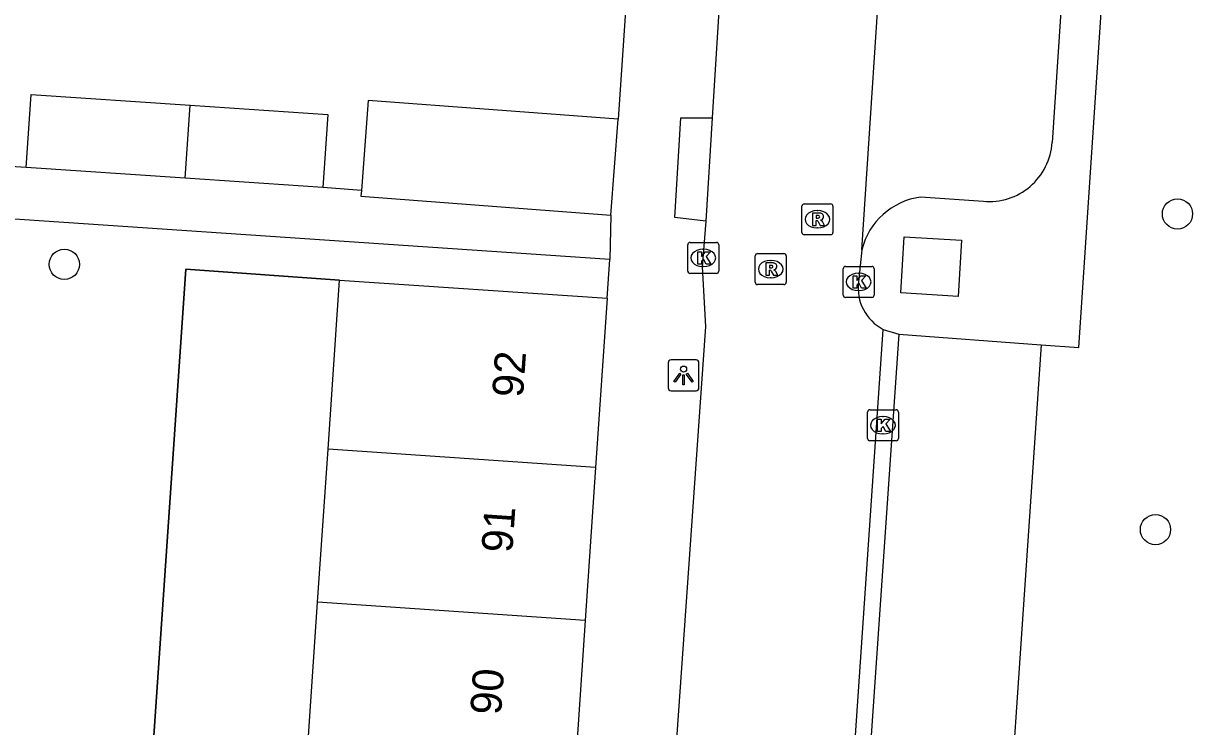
# Model space of a CAD drawing. Extents: x 161848 to 162726, y 385382 to 386521.
# Drawn here: x 162098.13 to 162135.92, y 385694.21 to 385716.95 of the extents above; entities that cross this region are included whole.
import ezdxf

# ---------------------------------------------------------------- set-up
doc = ezdxf.new("R2010")
doc.units = 0
for name, color, linetype in [('IMGEO_Boom', 7, 'Continuous'), ('IMGEO_Erf', 7, 'Continuous'), ('IMGEO_Kolk', 7, 'Continuous'), ('IMGEO_Lichtpunt', 7, 'Continuous'), ('IMGEO_Muur', 7, 'Continuous'), ('IMGEO_Pand', 7, 'Continuous'), ('IMGEO_Pand_nummerreeks', 7, 'Continuous'), ('IMGEO_Parkeervlak_open', 7, 'Continuous'), ('IMGEO_Rijbaan_lokaal_open', 7, 'Continuous'), ('IMGEO_Rioolput', 7, 'Continuous'), ('IMGEO_Voetpad_open', 7, 'Continuous')]:
    doc.layers.add(name, color=color, linetype=linetype)

msp = doc.modelspace()

# ---------------------------------------------------------------- linework, layer by layer
at = {"layer": 'IMGEO_Boom'}
for centre in [(162135.433, 385710.785), (162099.455, 385709.155), (162134.722, 385700.577)]:
    msp.add_circle(centre, 0.489, dxfattribs=at)
at = {"layer": 'IMGEO_Erf'}
msp.add_lwpolyline([(162108.35, 385708.642), (162103.379, 385708.994), (162101.257, 385678.025), (162106.241, 385677.689)], dxfattribs=at)
at = {"layer": 'IMGEO_Kolk'}
for p, q in [((162119.605, 385708.937), (162119.605, 385709.789)), ((162119.68, 385709.863), (162120.532, 385709.863)), ((162120.093, 385709.643), (162120.118, 385709.643)), ((162120.606, 385709.789), (162120.606, 385708.937)), ((162120.532, 385708.863), (162119.68, 385708.863)), ((162120.116, 385709.083), (162120.091, 385709.083)), ((162124.627, 385708.162), (162124.627, 385709.014)), ((162124.702, 385709.088), (162125.554, 385709.088)), ((162125.115, 385708.868), (162125.14, 385708.868)), ((162125.628, 385709.014), (162125.628, 385708.162)), ((162125.554, 385708.088), (162124.702, 385708.088)), ((162125.138, 385708.308), (162125.113, 385708.308)), ((162125.414, 385703.525), (162125.414, 385704.377)), ((162125.489, 385704.451), (162126.341, 385704.451)), ((162126.415, 385704.377), (162126.415, 385703.525)), ((162125.902, 385704.231), (162125.927, 385704.231)), ((162125.925, 385703.671), (162125.9, 385703.671)), ((162126.341, 385703.451), (162125.489, 385703.451))]:
    msp.add_line(p, q, dxfattribs=at)
for points in [[(162119.605, 385708.937), (162119.605, 385709.789)], [(162119.68, 385709.863), (162120.532, 385709.863)], [(162119.926, 385709.563), (162120.049, 385709.563), (162120.049, 385709.412), (162120.179, 385709.563), (162120.343, 385709.563), (162120.197, 385709.412), (162120.35, 385709.163), (162120.198, 385709.163), (162120.113, 385709.327), (162120.049, 385709.26), (162120.049, 385709.163), (162119.926, 385709.163), (162119.926, 385709.563)], [(162120.606, 385709.789), (162120.606, 385708.937)], [(162120.532, 385708.863), (162119.68, 385708.863)], [(162124.627, 385708.162), (162124.627, 385709.014)], [(162124.702, 385709.088), (162125.554, 385709.088)], [(162124.948, 385708.788), (162125.071, 385708.788), (162125.071, 385708.637), (162125.201, 385708.788), (162125.365, 385708.788), (162125.219, 385708.637), (162125.372, 385708.388), (162125.22, 385708.388), (162125.135, 385708.552), (162125.071, 385708.485), (162125.071, 385708.388), (162124.948, 385708.388), (162124.948, 385708.788)], [(162125.628, 385709.014), (162125.628, 385708.162)], [(162125.554, 385708.088), (162124.702, 385708.088)], [(162125.414, 385703.525), (162125.414, 385704.377)], [(162125.489, 385704.451), (162126.341, 385704.451)], [(162126.415, 385704.377), (162126.415, 385703.525)], [(162125.735, 385704.151), (162125.858, 385704.151), (162125.858, 385704), (162125.988, 385704.151), (162126.152, 385704.151), (162126.006, 385704), (162126.159, 385703.751), (162126.007, 385703.751), (162125.922, 385703.915), (162125.858, 385703.848), (162125.858, 385703.751), (162125.735, 385703.751), (162125.735, 385704.151)], [(162126.341, 385703.451), (162125.489, 385703.451)]]:
    msp.add_lwpolyline(points, dxfattribs=at)
for centre, start, end in [((162119.682, 385709.787), 91.552, 178.448), ((162119.682, 385709.787), 91.552, 178.448), ((162120.53, 385709.787), 1.552, 88.448), ((162120.53, 385709.787), 1.552, 88.448), ((162119.682, 385708.939), 181.552, 268.448), ((162119.682, 385708.939), 181.552, 268.448), ((162120.53, 385708.939), 271.552, 358.448), ((162120.53, 385708.939), 271.552, 358.448), ((162124.704, 385709.012), 91.552, 178.448), ((162124.704, 385709.012), 91.552, 178.448), ((162125.552, 385709.012), 1.552, 88.448), ((162125.552, 385709.012), 1.552, 88.448), ((162124.704, 385708.164), 181.552, 268.448), ((162124.704, 385708.164), 181.552, 268.448), ((162125.552, 385708.164), 271.552, 358.448), ((162125.552, 385708.164), 271.552, 358.448), ((162125.491, 385704.375), 91.552, 178.448), ((162125.491, 385704.375), 91.552, 178.448), ((162126.339, 385704.375), 1.552, 88.448), ((162126.339, 385704.375), 1.552, 88.448), ((162125.491, 385703.527), 181.552, 268.448), ((162125.491, 385703.527), 181.552, 268.448), ((162126.339, 385703.527), 271.552, 358.448), ((162126.339, 385703.527), 271.552, 358.448)]:
    msp.add_arc(centre, 0.0765, start, end, dxfattribs=at)
for centre, major_axis, ratio, start_param, end_param in [((162120.092, 385709.363), (-0.387, 0.002), 0.722429, 4.712389, 7.853982), ((162120.117, 385709.363), (-0.39, 0.002), 0.717154, 1.570796, 4.712389), ((162125.114, 385708.588), (-0.387, 0.002), 0.722429, 4.712389, 7.853982), ((162125.139, 385708.588), (-0.39, 0.002), 0.717154, 1.570796, 4.712389), ((162125.901, 385703.951), (-0.387, 0.002), 0.722429, 4.712389, 7.853982), ((162125.926, 385703.951), (-0.39, 0.002), 0.717154, 1.570796, 4.712389)]:
    msp.add_ellipse(centre, major_axis=major_axis, ratio=ratio, start_param=start_param, end_param=end_param, dxfattribs=at)
at = {"layer": 'IMGEO_Lichtpunt'}
for p, q in [((162118.971, 385705.969), (162118.971, 385705.162)), ((162118.971, 385705.969), (162118.971, 385705.162)), ((162119.873, 385706.064), (162119.065, 385706.064)), ((162119.873, 385706.064), (162119.065, 385706.064)), ((162119.967, 385705.162), (162119.967, 385705.969)), ((162119.967, 385705.162), (162119.967, 385705.969)), ((162119.065, 385705.068), (162119.873, 385705.068)), ((162119.065, 385705.068), (162119.873, 385705.068))]:
    msp.add_line(p, q, dxfattribs=at)
for points in [[(162119.345, 385705.633), (162119.384, 385705.605), (162119.196, 385705.343), (162119.158, 385705.37), (162119.345, 385705.633)], [(162119.447, 385705.585), (162119.494, 385705.585), (162119.494, 385705.263), (162119.447, 385705.263), (162119.447, 385705.585)], [(162119.557, 385705.605), (162119.595, 385705.632), (162119.782, 385705.37), (162119.743, 385705.342), (162119.557, 385705.605)]]:
    msp.add_lwpolyline(points, dxfattribs=at)
msp.add_circle((162119.47, 385705.767), 0.0994, dxfattribs=at)
for centre, start, end in [((162119.065, 385705.969), 90, 180), ((162119.065, 385705.969), 90, 180), ((162119.873, 385705.969), 0, 90), ((162119.873, 385705.969), 0, 90), ((162119.065, 385705.162), 180, 270), ((162119.065, 385705.162), 180, 270), ((162119.873, 385705.162), 270, 0), ((162119.873, 385705.162), 270, 360)]:
    msp.add_arc(centre, 0.0946, start, end, dxfattribs=at)
at = {"layer": 'IMGEO_Muur'}
msp.add_lwpolyline([(162106.241, 385677.689), (162101.257, 385678.025), (162103.379, 385708.994), (162108.35, 385708.642)], dxfattribs=at)
at = {"layer": 'IMGEO_Pand'}
for points in [[(162098.226, 385712.287), (162098.387, 385714.653), (162103.522, 385714.305)], [(162117.352, 385713.847), (162109.275, 385714.458), (162109.055, 385711.543)], [(162103.365, 385711.939), (162103.522, 385714.305)], [(162103.522, 385714.305), (162107.971, 385714.003), (162107.81, 385711.637)], [(162117.118, 385710.751), (162117.352, 385713.847)], [(162103.365, 385711.939), (162098.226, 385712.287)], [(162107.81, 385711.637), (162103.365, 385711.939)], [(162109.055, 385711.543), (162109.041, 385711.363), (162117.118, 385710.751)], [(162128.448, 385709.937), (162128.341, 385708.12), (162126.487, 385708.23), (162126.595, 385710.046), (162128.448, 385709.937)], [(162107.978, 385703.173), (162108.35, 385708.642)], [(162108.35, 385708.642), (162117.001, 385708.064)], [(162117.001, 385708.064), (162116.627, 385702.583)], [(162107.641, 385698.23), (162107.978, 385703.173)], [(162116.627, 385702.583), (162107.978, 385703.173)], [(162116.627, 385702.583), (162116.29, 385697.64)], [(162107.291, 385693.104), (162107.641, 385698.23)], [(162116.29, 385697.64), (162107.641, 385698.23)], [(162116.29, 385697.64), (162115.94, 385692.515)]]:
    msp.add_lwpolyline(points, dxfattribs=at)
at = {"layer": 'IMGEO_Parkeervlak_open'}
msp.add_lwpolyline([(162131.03, 385706.552), (162129.353, 385681.999)], dxfattribs=at)
at = {"layer": 'IMGEO_Rijbaan_lokaal_open'}
for points in [[(162120.507, 385734.873), (162121.694, 385734.795), (162120.393, 385713.89)], [(162125.234, 385709.628), (162126.713, 385732.225)], [(162120.393, 385713.89), (162120.186, 385710.552)], [(162120.186, 385710.552), (162120.068, 385709.079), (162120.176, 385707.147), (162118.427, 385682.147)], [(162125.234, 385709.628), (162125.128, 385708.588)], [(162124.197, 385681.746), (162125.923, 385707.05)], [(162126.424, 385706.892), (162124.693, 385681.723)], [(162125.923, 385707.05), (162126.424, 385706.892)]]:
    msp.add_lwpolyline(points, dxfattribs=at)
msp.add_arc((162126.618, 385708.384), 1.504, 172.187, 242.4823, dxfattribs=at)
at = {"layer": 'IMGEO_Rioolput'}
for p, q in [((162123.371, 385711.112), (162124.223, 385711.112)), ((162123.296, 385710.186), (162123.296, 385711.038)), ((162123.784, 385710.892), (162123.809, 385710.892)), ((162124.297, 385711.038), (162124.297, 385710.186)), ((162123.807, 385710.332), (162123.782, 385710.332)), ((162124.223, 385710.112), (162123.371, 385710.112)), ((162121.786, 385708.575), (162121.786, 385709.427)), ((162121.861, 385709.501), (162122.713, 385709.501)), ((162122.274, 385709.281), (162122.299, 385709.281)), ((162122.787, 385709.427), (162122.787, 385708.575)), ((162122.713, 385708.501), (162121.861, 385708.501)), ((162122.297, 385708.721), (162122.272, 385708.721))]:
    msp.add_line(p, q, dxfattribs=at)
for points in [[(162123.371, 385711.112), (162124.223, 385711.112)], [(162123.296, 385710.186), (162123.296, 385711.038)], [(162123.885, 385710.81), (162123.633, 385710.812), (162123.633, 385710.412)], [(162123.811, 385710.731), (162123.757, 385710.731), (162123.757, 385710.65)], [(162124.297, 385711.038), (162124.297, 385710.186)], [(162123.633, 385710.412), (162123.757, 385710.412), (162123.757, 385710.574), (162123.768, 385710.574)], [(162123.757, 385710.65), (162123.809, 385710.65)], [(162123.815, 385710.545), (162123.886, 385710.412), (162124.026, 385710.412), (162123.961, 385710.538)], [(162124.223, 385710.112), (162123.371, 385710.112)], [(162121.786, 385708.575), (162121.786, 385709.427)], [(162121.861, 385709.501), (162122.713, 385709.501)], [(162122.375, 385709.199), (162122.123, 385709.201), (162122.123, 385708.801)], [(162122.787, 385709.427), (162122.787, 385708.575)], [(162122.123, 385708.801), (162122.247, 385708.801), (162122.247, 385708.963), (162122.258, 385708.963)], [(162122.301, 385709.12), (162122.247, 385709.12), (162122.247, 385709.039)], [(162122.247, 385709.039), (162122.299, 385709.039)], [(162122.305, 385708.934), (162122.376, 385708.801), (162122.516, 385708.801), (162122.451, 385708.927)], [(162122.713, 385708.501), (162121.861, 385708.501)]]:
    msp.add_lwpolyline(points, dxfattribs=at)
for centre, radius, start, end in [((162123.373, 385711.036), 0.0765, 91.552, 178.448), ((162123.373, 385711.036), 0.0765, 91.552, 178.448), ((162124.221, 385711.036), 0.0765, 1.552, 88.448), ((162124.221, 385711.036), 0.0765, 1.552, 88.448), ((162123.817, 385710.635), 0.0964, 77.0061, 93.1865), ((162123.831, 385710.692), 0.0378, 276.6634, 79.6772), ((162123.884, 385710.7), 0.109, 350.3612, 89.416), ((162123.882, 385710.7), 0.112, 277.5842, 350.9817), ((162123.767, 385710.521), 0.0533, 26.0293, 88.6989), ((162123.793, 385710.839), 0.19, 274.7715, 282.9687), ((162123.866, 385710.485), 0.108, 29.5134, 73.7905), ((162123.373, 385710.188), 0.0765, 181.552, 268.448), ((162123.373, 385710.188), 0.0765, 181.552, 268.448), ((162124.221, 385710.188), 0.0765, 271.552, 358.448), ((162124.221, 385710.188), 0.0765, 271.552, 358.448), ((162121.863, 385709.425), 0.0765, 91.552, 178.448), ((162121.863, 385709.425), 0.0765, 91.552, 178.448), ((162122.374, 385709.089), 0.109, 350.3612, 89.416), ((162122.711, 385709.425), 0.0765, 1.552, 88.448), ((162122.711, 385709.425), 0.0765, 1.552, 88.448), ((162122.257, 385708.91), 0.0533, 26.0293, 88.6989), ((162122.283, 385709.228), 0.19, 274.7715, 282.9687), ((162122.307, 385709.024), 0.0964, 77.0061, 93.1865), ((162122.321, 385709.081), 0.0378, 276.6634, 79.6772), ((162122.372, 385709.089), 0.112, 277.5842, 350.9817), ((162122.356, 385708.874), 0.108, 29.5134, 73.7905), ((162121.863, 385708.577), 0.0765, 181.552, 268.448), ((162121.863, 385708.577), 0.0765, 181.552, 268.448), ((162122.711, 385708.577), 0.0765, 271.552, 358.448), ((162122.711, 385708.577), 0.0765, 271.552, 358.448)]:
    msp.add_arc(centre, radius, start, end, dxfattribs=at)
for centre, major_axis, ratio, start_param, end_param in [((162123.783, 385710.612), (-0.387, 0.002), 0.722429, 4.712389, 7.853982), ((162123.808, 385710.612), (-0.39, 0.002), 0.717154, 1.570796, 4.712389), ((162122.273, 385709.001), (-0.387, 0.002), 0.722429, 4.712389, 7.853982), ((162122.298, 385709.001), (-0.39, 0.002), 0.717154, 1.570796, 4.712389)]:
    msp.add_ellipse(centre, major_axis=major_axis, ratio=ratio, start_param=start_param, end_param=end_param, dxfattribs=at)
at = {"layer": 'IMGEO_Voetpad_open'}
for points in [[(162118.638, 385732.761), (162118.056, 385724.2), (162117.352, 385713.847)], [(162131.03, 385706.552), (162132.244, 385706.463), (162133.941, 385731.866)], [(162132.371, 385728.103), (162131.381, 385713.099)], [(162120.186, 385710.552), (162119.185, 385710.667), (162119.376, 385713.898), (162120.393, 385713.89)], [(162117.085, 385709.313), (162057.615, 385713.34)], [(162098.226, 385712.287), (162095.838, 385712.439)], [(162109.055, 385711.543), (162107.81, 385711.637)], [(162129.162, 385711.193), (162127.128, 385711.33)], [(162117.118, 385710.751), (162117.085, 385709.313)], [(162117.001, 385708.064), (162117.085, 385709.313)], [(162126.424, 385706.892), (162131.03, 385706.552)]]:
    msp.add_lwpolyline(points, dxfattribs=at)
for centre, radius, start, end in [((162129.348, 385713.221), 2.036, 264.7532, 356.5684), ((162127.428, 385709.091), 2.259, 97.6372, 166.2502)]:
    msp.add_arc(centre, radius, start, end, dxfattribs=at)

# ---------------------------------------------------------------- texts
at = {"layer": 'IMGEO_Pand_nummerreeks'}
for s, p in [('92', (162114.278, 385704.831)), ('91', (162113.932, 385699.809)), ('90', (162113.569, 385694.565))]:
    msp.add_text(s, height=1, rotation=86.0486, dxfattribs=at).set_placement(p)

doc.saveas('drawing.dxf')
